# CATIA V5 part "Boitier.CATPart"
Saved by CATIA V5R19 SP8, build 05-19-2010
Part number: Boitier
Bounding box of the stored display mesh (mm): x -7.3 to 21.8, y -11.7 to 11.7, z -1.5 to 5.5
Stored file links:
  D:\Travail\1 - ITEC_Turgot\00 - TP en cours de préparration\1-TP 4-9.2d Imprim3D_Uprint\Activité 4-9.2d_Imprim3D_FDM\Diviseur\Boitier.CATPart
  D:\Travail\1 - ITEC_Turgot\00 - TP en cours de préparration\1-TP 4-9.2d Imprim3D_Uprint\Activité 4-9.2d_Imprim3D_FDM\Diviseur\Diviseur_Turgot.CATProduct
  D:\Travail\1 - ITEC_Turgot\00 - TP en cours de préparration\1-TP 4-9.2d Imprim3D_Uprint\Activité 4-9.2d_Imprim3D_FDM\Diviseur\Croix.CATPart
  D:\Travail\1 - ITEC_Turgot\00 - TP en cours de préparration\1-TP 4-9.2d Imprim3D_Uprint\Activité 4-9.2d_Imprim3D_FDM\Diviseur\Roue.CATPart
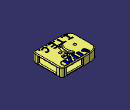
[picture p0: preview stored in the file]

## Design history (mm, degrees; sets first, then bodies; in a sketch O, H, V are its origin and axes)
Set1
  DatumCurve1 to DatumCurve3: linked copy from another document
  DatumSurface1: linked copy from another document
  DatumCurve4: linked copy from another document
  DatumSurface2: linked copy from another document
Body1 (main body)
  Sketch1 on xy-plane, origin (0, 0, 0), H (1, 0, 0), V (0, 1, 0)
    line L1 (21.8, 11.7) -> (0, 11.7)
    line L2 (-7.3, 9.1433) -> (-7.3, -9.1433)
    line L3 (0, -11.7) -> (21.8, -11.7)
    line L4 (21.8, -11.7) -> (21.8, 11.7)
    reference intersected line E1 through (0, 0) direction (0, 1) from yz-plane
    reference intersected line E2 through (0, 0) direction (-1, 0) from zx-plane
    arc A1 centre (0, 0) radius 11.7 from (-7.3, -9.1433) to (0, -11.7) ccw
    point P3 (0, 0)
    point P4 (0, 11.7)
    arc A2 centre (0, 0) radius 11.7 from (0, 11.7) to (-7.3, 9.1433) ccw
    circle A3 centre (0, 0) radius 1
    circle A4 centre (11.5, 0) radius 1
    reference projected circle E3 centre (11.5, 0) radius 1 from edge of DatumCurve2
    reference projected circle E4 centre (0, 0) radius 1 from edge of DatumCurve3
    distance L1 L3 = 23.4
    distance L4 L2 = 29.1
    distance E1 L2 = 7.3
    distance E2 L1 = 11.7
    horizontal: L1 H, L3 H
    vertical: L2 V, L4 V
    tangency: A1 L1, A1 L3
    coincidence: P3 V, A1 P4, A1 A2, A4 E3, A3 E4
  Pad1: profile Sketch1, direction (0, 0, -1), length 1.5
  Fillet1: radius 2, on edge [face of Pad1 from Sketch1.L3 | face of Pad1 from Sketch1.L4]; edge [face of Pad1 from Sketch1.L4 | face of Pad1 from Sketch1.L1]
  Fillet2: radius 4, on edge [face of Pad1 from Sketch1.L2 | face of Pad1 from Sketch1.A1]; edge [face of Pad1 from Sketch1.A2 | face of Pad1 from Sketch1.L2]
  Sketch2 on start face of Pad1, origin (0, 0, 0), H (1, 0, 0), V (0, 1, 0)
    offset line E1 (20.3, -9.7) -> (20.3, 9.7) from edge [face of Pad1 from Sketch1.L4 | start face of Pad1]
    offset line E2 (20.3, -9.7) -> (20.3, -7) from edge [face of Pad1 from Sketch1.L4 | start face of Pad1]
    offset line E3 (20.3, 7) -> (20.3, 9.7) from edge [face of Pad1 from Sketch1.L4 | start face of Pad1]
    offset arc E4 centre (19.8, 9.7) radius 0.5 from (20.3, 9.7) to (19.8, 10.2) ccw from edge [start face of Pad1 | face of Fillet1]
    offset line E5 (19.8, 10.2) -> (0, 10.2) from edge [face of Pad1 from Sketch1.L1 | start face of Pad1]
    offset line E6 (19.8, 10.2) -> (17.4, 10.2) from edge [face of Pad1 from Sketch1.L1 | start face of Pad1]
    offset line E7 (5.4, 10.2) -> (0, 10.2) from edge [face of Pad1 from Sketch1.L1 | start face of Pad1]
    point P6 (0, 10.2)
    offset line E8 (0, -10.2) -> (19.8, -10.2) from edge [face of Pad1 from Sketch1.L3 | start face of Pad1]
    offset line E9 (0, -10.2) -> (5.4, -10.2) from edge [face of Pad1 from Sketch1.L3 | start face of Pad1]
    offset line E10 (17.4, -10.2) -> (19.8, -10.2) from edge [face of Pad1 from Sketch1.L3 | start face of Pad1]
    point P7 (0, -10.2)
    offset arc E11 centre (19.8, -9.7) radius 0.5 from (19.8, -10.2) to (20.3, -9.7) ccw from edge [start face of Pad1 | face of Fillet1]
    projected line E12 (0, -11.7) -> (19.8, -11.7) from edge [face of Pad1 from Sketch1.L3 | start face of Pad1]
    projected line E13 (0, -11.7) -> (5.4, -11.7) from edge [face of Pad1 from Sketch1.L3 | start face of Pad1]
    projected line E14 (17.4, -11.7) -> (19.8, -11.7) from edge [face of Pad1 from Sketch1.L3 | start face of Pad1]
    projected arc E15 centre (19.8, -9.7) radius 2 from (19.8, -11.7) to (21.8, -9.7) ccw from edge [start face of Pad1 | face of Fillet1]
    projected line E16 (21.8, -9.7) -> (21.8, 9.7) from edge [face of Pad1 from Sketch1.L4 | start face of Pad1]
    projected line E17 (21.8, -9.7) -> (21.8, -7) from edge [face of Pad1 from Sketch1.L4 | start face of Pad1]
    projected line E18 (21.8, 7) -> (21.8, 9.7) from edge [face of Pad1 from Sketch1.L4 | start face of Pad1]
    projected arc E19 centre (19.8, 9.7) radius 2 from (21.8, 9.7) to (19.8, 11.7) ccw from edge [start face of Pad1 | face of Fillet1]
    projected line E20 (19.8, 11.7) -> (0, 11.7) from edge [face of Pad1 from Sketch1.L1 | start face of Pad1]
    projected line E21 (19.8, 11.7) -> (17.4, 11.7) from edge [face of Pad1 from Sketch1.L1 | start face of Pad1]
    projected line E22 (5.4, 11.7) -> (0, 11.7) from edge [face of Pad1 from Sketch1.L1 | start face of Pad1]
    line L1 (20.3, -7) -> (21.8, -7)
    line L2 (20.3, 7) -> (21.8, 7)
    line L3 (17.4, 10.2) -> (17.4, 11.7)
    line L4 (5.4, 10.2) -> (5.4, 11.7)
    line L5 (-5.3682, -8.3615) -> (-7.0453, -8.3615)
    line L6 (-5.3682, 8.3615) -> (-7.0453, 8.3615)
    point P21 (-7.0453, -8.3615)
    point P22 (-5.3682, -8.3615)
    point P23 (-5.3682, 8.3615)
    point P25 (-5.3682, 8.3615)
    point P26 (-7.0453, -8.3615)
    point P27 (-5.3682, -8.3615)
    reference intersected line E23 (21.8, 11.7) -> (21.8, -11.7) from face of Pad1 from Sketch1.L4
    point P28 (5.4, 11.7)
    point P29 (17.4, 11.7)
    point P30 (17.4, 10.2)
    point P31 (5.4, 10.2)
    point P32 (5.4, 10.2)
    point P33 (17.4, 11.7)
    point P34 (17.4, 10.2)
    point P35 (21.8, 7)
    point P36 (21.8, -7)
    point P37 (20.3, -7)
    point P38 (20.3, 7)
    point P39 (20.3, 7)
    point P40 (20.3, -7)
    point P41 (21.8, -7)
    line L7 (17.4, -11.7) -> (17.4, -10.2)
    line L8 (5.4, -11.7) -> (5.4, -10.2)
    point P42 (5.4, -11.7)
    point P43 (17.4, -11.7)
    point P44 (5.4, -10.2)
    point P45 (17.4, -10.2)
    point P46 (17.4, -10.2)
    point P47 (17.4, -11.7)
    point P48 (5.4, -11.7)
    point P49 (5.4, -10.2)
    projected arc E24 centre (0, 0) radius 11.7 from (0, 11.7) to (-5.0143, 10.571) ccw from edge [face of Pad1 from Sketch1.A2 | start face of Pad1]
    projected arc E25 centre (-3.3, 6.957) radius 4 from (-5.0143, 10.571) to (-7.3, 6.957) ccw from edge [start face of Pad1 | face of Fillet2]
    projected arc E26 centre (-3.3, 6.957) radius 4 from (-5.0143, 10.571) to (-7.0453, 8.3615) ccw from edge [start face of Pad1 | face of Fillet2]
    projected arc E27 centre (-3.3, -6.957) radius 4 from (-7.3, -6.957) to (-5.0143, -10.571) ccw from edge [start face of Pad1 | face of Fillet2]
    projected arc E28 centre (-3.3, -6.957) radius 4 from (-7.0453, -8.3615) to (-5.0143, -10.571) ccw from edge [start face of Pad1 | face of Fillet2]
    projected arc E29 centre (0, 0) radius 11.7 from (-5.0143, -10.571) to (0, -11.7) ccw from edge [face of Pad1 from Sketch1.A1 | start face of Pad1]
    offset arc E30 centre (0, 0) radius 10.2 from (0, 10.2) to (-4.3714, 9.2158) ccw from edge [face of Pad1 from Sketch1.A2 | start face of Pad1]
    point P59 (-4.3714, 9.2158)
    offset arc E31 centre (-3.3, 6.957) radius 2.5 from (-4.3714, 9.2158) to (-5.8, 6.957) ccw from edge [start face of Pad1 | face of Fillet2]
    offset arc E32 centre (-3.3, 6.957) radius 2.5 from (-4.3714, 9.2158) to (-5.3682, 8.3615) ccw from edge [start face of Pad1 | face of Fillet2]
    offset arc E33 centre (0, 0) radius 10.2 from (-4.3714, -9.2158) to (0, -10.2) ccw from edge [face of Pad1 from Sketch1.A1 | start face of Pad1]
    point P62 (-4.3714, -9.2158)
    offset arc E34 centre (-3.3, -6.957) radius 2.5 from (-5.8, -6.957) to (-4.3714, -9.2158) ccw from edge [start face of Pad1 | face of Fillet2]
    offset arc E35 centre (-3.3, -6.957) radius 2.5 from (-5.3682, -8.3615) to (-4.3714, -9.2158) ccw from edge [start face of Pad1 | face of Fillet2]
    distance L5 L6 = 16.723
    distance L5 O = 8.3615
    distance L4 L3 = 12
    distance L3 E23 = 4.4
    distance L1 L2 = 14
    distance H L1 = 7
    parallelism: L3 E1, L5 E8, L6 E5
    coincidence: L5 P21, L5 P22, L6 P23, E20 P28, L3 P29, L3 P30, L4 P31, E5 P32, E20 P33, E5 P34, E16 P35, L1 P36, L1 P37, L2 P38, E1 P39, E1 P40, E16 P41, L4 L8, L7 L3, L8 P42, L7 P43, L8 P44, L7 P45, E8 P46, E12 P47, E12 P48, E8 P49, P21 P26, P22 P27, P23 P25, P29 P33, P30 P34, P31 P32, P36 P41, P37 P40, P38 P39, P42 P48, P43 P47, P44 P49, P45 P46, E30 P6, E31 P59, E33 P7, E34 P62
    vertical: L8 V
    tangency: E30 E5, E31 E30, E33 E5, E34 E33
  Pad2: profile Sketch2, direction (0, 0, 1), up to face of DatumSurface2
  Sketch3 on end face of Pad2, origin (0, 0, 4), H (1, 0, 0), V (0, 1, 0)
    projected line E1 (-7.3, 6.957) -> (-7.3, -6.957) from edge [end face of Pad1 | face of Pad1 from Sketch1.L2]
    projected line E2 (0, -11.7) -> (19.8, -11.7) from edge [end face of Pad1 | face of Pad2]
    projected arc E3 centre (19.8, -9.7) radius 2 from (19.8, -11.7) to (21.8, -9.7) ccw from edge [end face of Pad1 | face of Pad2]
    projected line E4 (21.8, -9.7) -> (21.8, 9.7) from edge [end face of Pad1 | face of Pad2]
    projected arc E5 centre (19.8, 9.7) radius 2 from (21.8, 9.7) to (19.8, 11.7) ccw from edge [end face of Pad1 | face of Pad2]
    projected line E6 (19.8, 11.7) -> (0, 11.7) from edge [end face of Pad1 | face of Pad2]
    projected arc E7 centre (0, 0) radius 11.7 from (0, 11.7) to (-5.0143, 10.571) ccw from edge [face of Pad2 | end face of Pad2]
    projected arc E8 centre (-3.3, 6.957) radius 4 from (-5.0143, 10.571) to (-7.3, 6.957) ccw from edge [end face of Pad1 | face of Pad2]
    projected arc E9 centre (-3.3, -6.957) radius 4 from (-7.3, -6.957) to (-5.0143, -10.571) ccw from edge [end face of Pad1 | face of Pad2]
    projected arc E10 centre (0, 0) radius 11.7 from (-5.0143, -10.571) to (0, -11.7) ccw from edge [end face of Pad1 | face of Pad2]
  Pad3: profile Sketch3, direction (0, 0, 1), length 1.5
  Sketch4 on end face of Pad3, origin (0, 0, 5.5), H (1, 0, 0), V (0, 1, 0)
    construction arc A1 centre (11.5, 0) radius 3.3683 from (13.2483, 2.879) to (9.7973, 2.9063) ccw
    point P1 (11.5, 0)
    arc A2 centre (11.5, 0) radius 3 from (11.9919, 2.9594) to (11.0081, 2.9594) ccw
    arc A3 centre (11.5, 0) radius 5.5 from (10.4956, 5.4075) to (12.5044, 5.4075) cw
    line L1 (13.3005, 3.8611) -> (13.1692, 3.5796)
    arc A4 centre (12.3035, 4.326) radius 1.1 from (12.5044, 5.4075) to (13.3005, 3.8611) cw
    arc A5 centre (12.1723, 4.0445) radius 1.1 from (11.9919, 2.9594) to (13.1692, 3.5796) ccw
    line L2 (9.6995, 3.8611) -> (9.8308, 3.5796)
    arc A6 centre (10.6965, 4.326) radius 1.1 from (10.4956, 5.4075) to (9.6995, 3.8611) ccw
    arc A7 centre (10.8277, 4.0445) radius 1.1 from (11.0081, 2.9594) to (9.8308, 3.5796) cw
    reference intersected line E1 through (0, 0) direction (0, 1) from yz-plane
    construction arc A8 centre (0, 0) radius 8.1317 from (5.8051, -5.6943) to (6.2292, 5.2269) ccw
    point P17 (6.2292, 5.2269)
    arc A9 centre (0, 0) radius 7.1317 from (5.7518, -4.2164) to (5.7518, 4.2164) ccw
    arc A10 centre (0, 0) radius 9.1317 from (7.3235, 5.4547) to (7.3235, -5.4547) cw
    line L3 (5.8336, 4.895) -> (6.6011, 5.539)
    point P18 (6.9953, 5.8697)
    line L4 (5.8336, -4.895) -> (6.6011, -5.539)
    point P19 (6.9953, -5.8697)
    arc A11 centre (6.9225, 5.156) radius 0.5 from (7.3235, 5.4547) to (6.6011, 5.539) ccw
    arc A12 centre (6.155, 4.512) radius 0.5 from (5.7518, 4.2164) to (5.8336, 4.895) cw
    arc A13 centre (6.155, -4.512) radius 0.5 from (5.7518, -4.2164) to (5.8336, -4.895) ccw
    arc A14 centre (6.9225, -5.156) radius 0.5 from (7.3235, -5.4547) to (6.6011, -5.539) cw
    reference projected circle E2 centre (11.5, 0) radius 1 from edge [face of Pad1 from Sketch1.A4 | end face of Pad1]
    projected circle E3 centre (11.5, 0) radius 1 from edge [face of Pad1 from Sketch1.A4 | end face of Pad1]
    projected circle E4 centre (0, 0) radius 1 from edge [face of Pad1 from Sketch1.A3 | end face of Pad1]
    radius A2 = 3
    radius A3 = 5.5
    radius A4 = 1.1
    radius A5 = 1.1
    radius A6 = 1.1
    radius A7 = 1.1
    angle L1 L2 = 50
    angle L1 E1 = 25 {= Sketch4.angle(L1 L2) /2}
    radius A11 = 0.5
    radius A12 = 0.5
    radius A13 = 0.5
    radius A14 = 0.5
    distance A8 A10 = 1
    distance A8 A9 = 1
    angle L3 H = 40
    angle L4 H = 40
    distance A9 O = 7.1317
    concentricity: A2 P1, A3 P1, A9 O, A10 O, A3 E2
    coincidence: L1 P1, L2 P1, P18 A10, L3 P17, P19 A10, L3 P18, L4 P19, O L3, L4 O
    tangency: A4 L1, A4 A3, A5 L1, A5 A2, A6 L2, A6 A3, A7 L2, A7 A2, A8 A1, A11 A10, A11 L3, A12 L3, A12 A9, A13 A9, A13 L4, A14 L4, A14 A10
  Pocket1: profile Sketch4, direction (0, 0, -1), through (limit type 6)
  Fillet3: radius 0.6, on edge [face of Pad3 | end face of Pad3]; edge [end face of Pad3 | face of Pocket1 from Sketch4.A3]; edge [end face of Pad1 | face of Pad3]; edge [face of Pad2 from Sketch2.L8 | face of Pad3]; edge [start face of Pad3 | face of Pad3] (x3); edge [face of Pad3 | face of Pad2 from Sketch2.L7]; edge [face of Pad3 | start face of Pad1] (x3); edge [face of Pad2 from Sketch2.L7 | face of Pad2 from Sketch2.E10]; edge [face of Pad2 from Sketch2.E10 | face of Pad2 from Sketch2.L8]; edge [face of Pad2 from Sketch2.L1 | face of Pad3]; edge [face of Pad2 from Sketch2.E3 | face of Pad2 from Sketch2.L1]; edge [face of Pad2 from Sketch2.L2 | face of Pad2 from Sketch2.E3]; edge [face of Pad3 | face of Pad2 from Sketch2.L2]; edge [face of Pad3 | face of Pad2 from Sketch2.L4]; edge [face of Pad2 from Sketch2.L4 | face of Pad2 from Sketch2.E7]; edge [face of Pad2 from Sketch2.E7 | face of Pad2 from Sketch2.L3]; edge [face of Pad2 from Sketch2.L3 | face of Pad3]; edge [start face of Pad3 | face of Pad3 from Sketch3.E1]; edge [face of Pad1 from Sketch1.L2 | start face of Pad1]; edge [end face of Pad3 | face of Pocket1 from Sketch4.A9]
  Sketch5 on end face of Pad3, origin (0, 0, 5.5), H (1, 0, 0), V (0, 1, 0)
    polyline C1
    polyline C2
    polyline C3
    polyline C4
    polyline C5
    polyline C6
    polyline C7
    polyline C8
    polyline C9
    polyline C10
    polyline C11
    polyline C12
    polyline C13
    polyline C14
  Pocket2: profile Sketch5, direction (0, 0, -1), length 0.5
  Sketch6 on end face of Pad1, origin (0, 0, -1.5), H (1, 0, 0), V (0, -1, 0)
    polyline C1
    polyline C2
    polyline C3
    polyline C4
    polyline C5
    polyline C6
    polyline C7
    polyline C8
    polyline C9
    polyline C10
    polyline C11
    polyline C12
    polyline C13
    polyline C14
  Pocket3: profile Sketch6, direction (0, 0, 1), length 0.5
